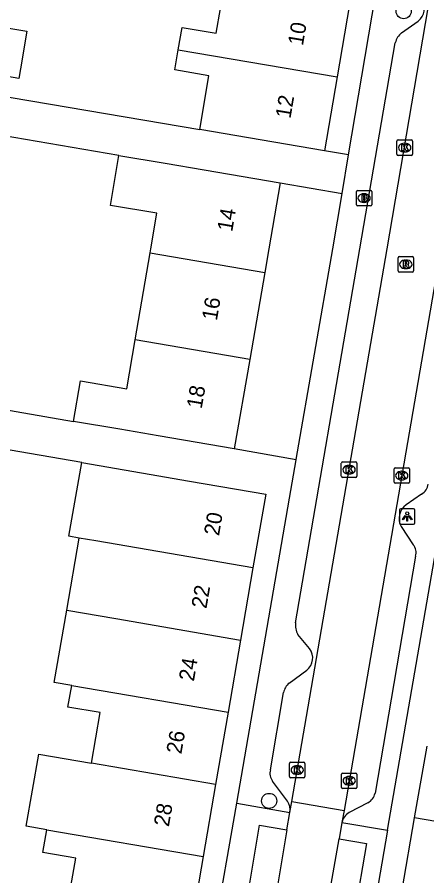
# Model space of a CAD drawing. Extents: x 159822 to 160765, y 380693 to 381634.
# Drawn here: x 160104.9 to 160131.4, y 380959.3 to 381015 of the extents above; entities that cross this region are included whole.
import ezdxf

# ---------------------------------------------------------------- set-up
doc = ezdxf.new("R2010")
doc.units = 0
for name, color, linetype in [('IMGEO_Boom', 7, 'Continuous'), ('IMGEO_Brandkraan', 7, 'Continuous'), ('IMGEO_Kolk', 7, 'Continuous'), ('IMGEO_Lichtpunt', 7, 'Continuous'), ('IMGEO_Pand', 7, 'Continuous'), ('IMGEO_Pand_nummerreeks', 7, 'Continuous'), ('IMGEO_Rijbaan_lokaal_open', 7, 'Continuous'), ('IMGEO_Rioolput', 7, 'Continuous'), ('IMGEO_Voetpad_open', 7, 'Continuous')]:
    doc.layers.add(name, color=color, linetype=linetype)

msp = doc.modelspace()

# ---------------------------------------------------------------- linework, layer by layer
at = {"layer": 'IMGEO_Boom'}
for centre in [(160129.945, 381015.406), (160121.229, 380964.193)]:
    msp.add_circle(centre, 0.489, dxfattribs=at)
at = {"layer": 'IMGEO_Brandkraan'}
for p, q in [((160126.879, 381002.859), (160126.879, 381003.711)), ((160126.954, 381003.785), (160127.806, 381003.785)), ((160127.367, 381003.565), (160127.392, 381003.565)), ((160127.88, 381003.711), (160127.88, 381002.859)), ((160127.39, 381003.005), (160127.365, 381003.005)), ((160127.806, 381002.785), (160126.954, 381002.785))]:
    msp.add_line(p, q, dxfattribs=at)
for points in [[(160126.879, 381002.859), (160126.879, 381003.711)], [(160126.954, 381003.785), (160127.806, 381003.785)], [(160127.88, 381003.711), (160127.88, 381002.859)], [(160127.227, 381003.485), (160127.227, 381003.085), (160127.44, 381003.085)], [(160127.458, 381003.485), (160127.227, 381003.485)], [(160127.406, 381003.404), (160127.352, 381003.404), (160127.352, 381003.328)], [(160127.352, 381003.328), (160127.405, 381003.328)], [(160127.414, 381003.252), (160127.352, 381003.252), (160127.352, 381003.171)], [(160127.352, 381003.171), (160127.414, 381003.171)], [(160127.806, 381002.785), (160126.954, 381002.785)]]:
    msp.add_lwpolyline(points, dxfattribs=at)
for centre, radius, start, end in [((160126.956, 381003.709), 0.0765, 91.552, 178.448), ((160126.956, 381003.709), 0.0765, 91.552, 178.448), ((160127.804, 381003.709), 0.0765, 1.552, 88.448), ((160127.804, 381003.709), 0.0765, 1.552, 88.448), ((160127.407, 381003.366), 0.0379, 267.8285, 90.9355), ((160127.415, 381003.211), 0.0404, 269.8759, 90.5077), ((160127.446, 381003.336), 0.251, 268.6676, 293.5347), ((160127.462, 381003.34), 0.145, 59.4692, 91.5367), ((160127.487, 381003.387), 0.0922, 285.5137, 58.1501), ((160127.492, 381003.195), 0.105, 301.3115, 78.989), ((160126.956, 381002.861), 0.0765, 181.552, 268.448), ((160126.956, 381002.861), 0.0765, 181.552, 268.448), ((160127.804, 381002.861), 0.0765, 271.552, 358.448), ((160127.804, 381002.861), 0.0765, 271.552, 358.448)]:
    msp.add_arc(centre, radius, start, end, dxfattribs=at)
for centre, major_axis, ratio, start_param, end_param in [((160127.366, 381003.285), (-0.387, 0.002), 0.722429, 4.712389, 7.853982), ((160127.391, 381003.285), (-0.39, 0.002), 0.717154, 1.570796, 4.712389)]:
    msp.add_ellipse(centre, major_axis=major_axis, ratio=ratio, start_param=start_param, end_param=end_param, dxfattribs=at)
at = {"layer": 'IMGEO_Kolk'}
for p, q in [((160129.51, 381006.134), (160129.51, 381006.986)), ((160129.585, 381007.06), (160130.437, 381007.06)), ((160130.511, 381006.986), (160130.511, 381006.134)), ((160129.998, 381006.84), (160130.023, 381006.84)), ((160130.437, 381006.06), (160129.585, 381006.06)), ((160130.021, 381006.28), (160129.996, 381006.28)), ((160125.907, 380985.249), (160125.907, 380986.101)), ((160125.982, 380986.175), (160126.834, 380986.175)), ((160126.395, 380985.955), (160126.42, 380985.955)), ((160126.908, 380986.101), (160126.908, 380985.249)), ((160129.321, 380984.867), (160129.321, 380985.719)), ((160129.396, 380985.793), (160130.248, 380985.793)), ((160130.322, 380985.719), (160130.322, 380984.867)), ((160126.834, 380985.175), (160125.982, 380985.175)), ((160126.418, 380985.395), (160126.393, 380985.395)), ((160129.809, 380985.573), (160129.834, 380985.573)), ((160130.248, 380984.793), (160129.396, 380984.793)), ((160129.832, 380985.013), (160129.807, 380985.013)), ((160122.547, 380965.769), (160122.547, 380966.621)), ((160122.622, 380966.695), (160123.474, 380966.695)), ((160123.035, 380966.475), (160123.06, 380966.475)), ((160123.548, 380966.621), (160123.548, 380965.769)), ((160123.474, 380965.695), (160122.622, 380965.695)), ((160123.058, 380965.915), (160123.033, 380965.915)), ((160125.916, 380965.07), (160125.916, 380965.922)), ((160125.991, 380965.996), (160126.843, 380965.996)), ((160126.404, 380965.776), (160126.429, 380965.776)), ((160126.917, 380965.922), (160126.917, 380965.07)), ((160126.427, 380965.216), (160126.402, 380965.216)), ((160126.843, 380964.996), (160125.991, 380964.996))]:
    msp.add_line(p, q, dxfattribs=at)
for points in [[(160129.51, 381006.134), (160129.51, 381006.986)], [(160129.585, 381007.06), (160130.437, 381007.06)], [(160130.511, 381006.986), (160130.511, 381006.134)], [(160129.831, 381006.76), (160129.954, 381006.76), (160129.954, 381006.609), (160130.084, 381006.76), (160130.248, 381006.76), (160130.102, 381006.609), (160130.255, 381006.36), (160130.103, 381006.36), (160130.018, 381006.524), (160129.954, 381006.457), (160129.954, 381006.36), (160129.831, 381006.36), (160129.831, 381006.76)], [(160130.437, 381006.06), (160129.585, 381006.06)], [(160125.907, 380985.249), (160125.907, 380986.101)], [(160125.982, 380986.175), (160126.834, 380986.175)], [(160126.228, 380985.875), (160126.351, 380985.875), (160126.351, 380985.724), (160126.481, 380985.875), (160126.645, 380985.875), (160126.499, 380985.724), (160126.652, 380985.475), (160126.5, 380985.475), (160126.415, 380985.639), (160126.351, 380985.572), (160126.351, 380985.475), (160126.228, 380985.475), (160126.228, 380985.875)], [(160126.908, 380986.101), (160126.908, 380985.249)], [(160129.321, 380984.867), (160129.321, 380985.719)], [(160129.396, 380985.793), (160130.248, 380985.793)], [(160130.322, 380985.719), (160130.322, 380984.867)], [(160126.834, 380985.175), (160125.982, 380985.175)], [(160129.642, 380985.493), (160129.765, 380985.493), (160129.765, 380985.342), (160129.895, 380985.493), (160130.059, 380985.493), (160129.913, 380985.342), (160130.066, 380985.093), (160129.914, 380985.093), (160129.829, 380985.257), (160129.765, 380985.19), (160129.765, 380985.093), (160129.642, 380985.093), (160129.642, 380985.493)], [(160130.248, 380984.793), (160129.396, 380984.793)], [(160122.547, 380965.769), (160122.547, 380966.621)], [(160122.622, 380966.695), (160123.474, 380966.695)], [(160122.868, 380966.395), (160122.991, 380966.395), (160122.991, 380966.244), (160123.121, 380966.395), (160123.285, 380966.395), (160123.139, 380966.244), (160123.292, 380965.995), (160123.14, 380965.995), (160123.055, 380966.159), (160122.991, 380966.092), (160122.991, 380965.995), (160122.868, 380965.995), (160122.868, 380966.395)], [(160123.548, 380966.621), (160123.548, 380965.769)], [(160123.474, 380965.695), (160122.622, 380965.695)], [(160125.916, 380965.07), (160125.916, 380965.922)], [(160125.991, 380965.996), (160126.843, 380965.996)], [(160126.237, 380965.696), (160126.36, 380965.696), (160126.36, 380965.545), (160126.49, 380965.696), (160126.654, 380965.696), (160126.508, 380965.545), (160126.661, 380965.296), (160126.509, 380965.296), (160126.424, 380965.46), (160126.36, 380965.393), (160126.36, 380965.296), (160126.237, 380965.296), (160126.237, 380965.696)], [(160126.917, 380965.922), (160126.917, 380965.07)], [(160126.843, 380964.996), (160125.991, 380964.996)]]:
    msp.add_lwpolyline(points, dxfattribs=at)
for centre, start, end in [((160129.587, 381006.984), 91.552, 178.448), ((160129.587, 381006.984), 91.552, 178.448), ((160130.435, 381006.984), 1.552, 88.448), ((160130.435, 381006.984), 1.552, 88.448), ((160129.587, 381006.136), 181.552, 268.448), ((160129.587, 381006.136), 181.552, 268.448), ((160130.435, 381006.136), 271.552, 358.448), ((160130.435, 381006.136), 271.552, 358.448), ((160125.984, 380986.099), 91.552, 178.448), ((160125.984, 380986.099), 91.552, 178.448), ((160126.832, 380986.099), 1.552, 88.448), ((160126.832, 380986.099), 1.552, 88.448), ((160129.398, 380985.717), 91.552, 178.448), ((160129.398, 380985.717), 91.552, 178.448), ((160130.246, 380985.717), 1.552, 88.448), ((160130.246, 380985.717), 1.552, 88.448), ((160125.984, 380985.251), 181.552, 268.448), ((160125.984, 380985.251), 181.552, 268.448), ((160126.832, 380985.251), 271.552, 358.448), ((160126.832, 380985.251), 271.552, 358.448), ((160129.398, 380984.869), 181.552, 268.448), ((160129.398, 380984.869), 181.552, 268.448), ((160130.246, 380984.869), 271.552, 358.448), ((160130.246, 380984.869), 271.552, 358.448), ((160122.624, 380966.619), 91.552, 178.448), ((160122.624, 380966.619), 91.552, 178.448), ((160123.472, 380966.619), 1.552, 88.448), ((160123.472, 380966.619), 1.552, 88.448), ((160122.624, 380965.771), 181.552, 268.448), ((160122.624, 380965.771), 181.552, 268.448), ((160123.472, 380965.771), 271.552, 358.448), ((160123.472, 380965.771), 271.552, 358.448), ((160125.993, 380965.92), 91.552, 178.448), ((160125.993, 380965.92), 91.552, 178.448), ((160126.841, 380965.92), 1.552, 88.448), ((160126.841, 380965.92), 1.552, 88.448), ((160125.993, 380965.072), 181.552, 268.448), ((160125.993, 380965.072), 181.552, 268.448), ((160126.841, 380965.072), 271.552, 358.448), ((160126.841, 380965.072), 271.552, 358.448)]:
    msp.add_arc(centre, 0.0765, start, end, dxfattribs=at)
for centre, major_axis, ratio, start_param, end_param in [((160129.997, 381006.56), (-0.387, 0.002), 0.722429, 4.712389, 7.853982), ((160130.022, 381006.56), (-0.39, 0.002), 0.717154, 1.570796, 4.712389), ((160126.394, 380985.675), (-0.387, 0.002), 0.722429, 4.712389, 7.853982), ((160126.419, 380985.675), (-0.39, 0.002), 0.717154, 1.570796, 4.712389), ((160129.808, 380985.293), (-0.387, 0.002), 0.722429, 4.712389, 7.853982), ((160129.833, 380985.293), (-0.39, 0.002), 0.717154, 1.570796, 4.712389), ((160123.034, 380966.195), (-0.387, 0.002), 0.722429, 4.712389, 7.853982), ((160123.059, 380966.195), (-0.39, 0.002), 0.717154, 1.570796, 4.712389), ((160126.403, 380965.496), (-0.387, 0.002), 0.722429, 4.712389, 7.853982), ((160126.428, 380965.496), (-0.39, 0.002), 0.717154, 1.570796, 4.712389)]:
    msp.add_ellipse(centre, major_axis=major_axis, ratio=ratio, start_param=start_param, end_param=end_param, dxfattribs=at)
at = {"layer": 'IMGEO_Lichtpunt'}
for p, q in [((160129.678, 380983.039), (160129.678, 380982.232)), ((160129.678, 380983.039), (160129.678, 380982.232)), ((160130.58, 380983.134), (160129.772, 380983.134)), ((160130.58, 380983.134), (160129.772, 380983.134)), ((160130.674, 380982.232), (160130.674, 380983.039)), ((160130.674, 380982.232), (160130.674, 380983.039)), ((160129.772, 380982.138), (160130.58, 380982.138)), ((160129.772, 380982.138), (160130.58, 380982.138))]:
    msp.add_line(p, q, dxfattribs=at)
for points in [[(160130.052, 380982.703), (160130.091, 380982.675), (160129.903, 380982.413), (160129.865, 380982.44), (160130.052, 380982.703)], [(160130.154, 380982.655), (160130.201, 380982.655), (160130.201, 380982.333), (160130.154, 380982.333), (160130.154, 380982.655)], [(160130.264, 380982.675), (160130.302, 380982.702), (160130.489, 380982.44), (160130.45, 380982.412), (160130.264, 380982.675)]]:
    msp.add_lwpolyline(points, dxfattribs=at)
msp.add_circle((160130.177, 380982.837), 0.0994, dxfattribs=at)
for centre, start, end in [((160129.772, 380983.039), 90, 180), ((160129.772, 380983.039), 90, 180), ((160130.58, 380983.039), 0, 90), ((160130.58, 380983.039), 0, 90), ((160129.772, 380982.232), 180, 270), ((160129.772, 380982.232), 180, 270), ((160130.58, 380982.232), 270, 0), ((160130.58, 380982.232), 270, 360)]:
    msp.add_arc(centre, 0.0946, start, end, dxfattribs=at)
at = {"layer": 'IMGEO_Pand'}
for points in [[(160115.347, 381012.91), (160115.593, 381014.354), (160117.806, 381013.976), (160118.359, 381017.215)], [(160126.434, 381015.835), (160125.634, 381011.153)], [(160103.071, 381014.534), (160105.535, 381014.112), (160105.118, 381011.678), (160105.01, 381011.047), (160102.548, 381011.47), (160102.821, 381013.068)], [(160116.737, 381007.729), (160117.334, 381011.222), (160115.123, 381011.6), (160115.347, 381012.91)], [(160115.347, 381012.91), (160125.634, 381011.153)], [(160125.634, 381011.153), (160124.813, 381006.349)], [(160124.813, 381006.349), (160119.885, 381007.191), (160116.737, 381007.729)], [(160113.513, 380999.74), (160113.557, 381000), (160113.95, 381002.304), (160110.944, 381002.818), (160111.498, 381006.056)], [(160111.498, 381006.056), (160114.502, 381005.543), (160117.017, 381005.113), (160121.945, 381004.271)], [(160121.945, 381004.271), (160121.209, 381000), (160120.944, 380998.46)], [(160112.551, 380994.1), (160113.513, 380999.74)], [(160113.513, 380999.74), (160120.944, 380998.46)], [(160120.944, 380998.46), (160119.973, 380992.822)], [(160108.566, 380988.808), (160109.018, 380991.434), (160112.008, 380990.919), (160112.551, 380994.1)], [(160119.973, 380992.822), (160112.551, 380994.1)], [(160119.973, 380992.822), (160118.973, 380987.015)], [(160118.973, 380987.015), (160114.046, 380987.864), (160111.56, 380988.292), (160108.566, 380988.808)], [(160108.925, 380981.239), (160108.262, 380981.353), (160109.089, 380986.143)], [(160109.089, 380986.143), (160112.968, 380985.475), (160116.082, 380984.939), (160121.009, 380984.09), (160120.184, 380979.3)], [(160108.119, 380976.558), (160108.925, 380981.239)], [(160120.184, 380979.3), (160109.994, 380981.055), (160108.925, 380981.239)], [(160120.184, 380979.3), (160119.378, 380974.619)], [(160108.44, 380971.682), (160107.313, 380971.876), (160108.119, 380976.558)], [(160108.119, 380976.558), (160111.294, 380976.011), (160119.378, 380974.619)], [(160119.378, 380974.619), (160118.572, 380969.938)], [(160109.713, 380966.643), (160110.277, 380969.921), (160108.198, 380970.279), (160108.44, 380971.682)], [(160108.44, 380971.682), (160118.572, 380969.938)], [(160118.572, 380969.938), (160117.766, 380965.256)], [(160130.656, 380963.083), (160131.459, 380967.745)], [(160106.829, 380962.32), (160105.5, 380962.549), (160106.307, 380967.23), (160109.713, 380966.643)], [(160117.766, 380965.256), (160109.713, 380966.643)], [(160117.766, 380965.256), (160116.96, 380960.575)], [(160129.853, 380958.422), (160130.656, 380963.083)], [(160138.691, 380961.7), (160130.656, 380963.083)], [(160108.129, 380957.163), (160108.701, 380960.485), (160106.576, 380960.851), (160106.829, 380962.32)], [(160106.829, 380962.32), (160116.96, 380960.575)], [(160116.96, 380960.575), (160116.135, 380955.784)]]:
    msp.add_lwpolyline(points, dxfattribs=at)
at = {"layer": 'IMGEO_Rijbaan_lokaal_open'}
for points in [[(160122.694, 380964.146), (160128.881, 381000), (160134.55, 381033.44)], [(160137.998, 381032.804), (160132.353, 381000), (160126.083, 380963.562)], [(160122.575, 380963.442), (160122.694, 380964.146)], [(160122.694, 380964.146), (160126.083, 380963.562)], [(160122.386, 380962.321), (160122.575, 380963.442)], [(160126.083, 380963.562), (160125.95, 380962.792)], [(160122.386, 380962.321), (160121.639, 380957.894)], [(160125.95, 380962.792), (160125.767, 380961.739)], [(160124.999, 380957.316), (160125.767, 380961.739)]]:
    msp.add_lwpolyline(points, dxfattribs=at)
at = {"layer": 'IMGEO_Rioolput'}
for p, q in [((160129.585, 380998.566), (160129.585, 380999.418)), ((160129.66, 380999.492), (160130.512, 380999.492)), ((160130.073, 380999.272), (160130.098, 380999.272)), ((160130.586, 380999.418), (160130.586, 380998.566)), ((160130.512, 380998.492), (160129.66, 380998.492)), ((160130.096, 380998.712), (160130.071, 380998.712))]:
    msp.add_line(p, q, dxfattribs=at)
for points in [[(160129.585, 380998.566), (160129.585, 380999.418)], [(160129.66, 380999.492), (160130.512, 380999.492)], [(160130.174, 380999.19), (160129.922, 380999.192), (160129.922, 380998.792)], [(160130.1, 380999.111), (160130.046, 380999.111), (160130.046, 380999.03)], [(160130.586, 380999.418), (160130.586, 380998.566)], [(160130.512, 380998.492), (160129.66, 380998.492)], [(160129.922, 380998.792), (160130.046, 380998.792), (160130.046, 380998.954), (160130.057, 380998.954)], [(160130.046, 380999.03), (160130.098, 380999.03)], [(160130.104, 380998.925), (160130.175, 380998.792), (160130.315, 380998.792), (160130.25, 380998.918)]]:
    msp.add_lwpolyline(points, dxfattribs=at)
for centre, radius, start, end in [((160129.662, 380999.416), 0.0765, 91.552, 178.448), ((160129.662, 380999.416), 0.0765, 91.552, 178.448), ((160130.106, 380999.015), 0.0964, 77.0061, 93.1865), ((160130.12, 380999.072), 0.0378, 276.6634, 79.6772), ((160130.173, 380999.08), 0.109, 350.3612, 89.416), ((160130.171, 380999.08), 0.112, 277.5842, 350.9817), ((160130.51, 380999.416), 0.0765, 1.552, 88.448), ((160130.51, 380999.416), 0.0765, 1.552, 88.448), ((160129.662, 380998.568), 0.0765, 181.552, 268.448), ((160129.662, 380998.568), 0.0765, 181.552, 268.448), ((160130.056, 380998.901), 0.0533, 26.0293, 88.6989), ((160130.082, 380999.219), 0.19, 274.7715, 282.9687), ((160130.155, 380998.865), 0.108, 29.5134, 73.7905), ((160130.51, 380998.568), 0.0765, 271.552, 358.448), ((160130.51, 380998.568), 0.0765, 271.552, 358.448)]:
    msp.add_arc(centre, radius, start, end, dxfattribs=at)
for centre, major_axis, ratio, start_param, end_param in [((160130.072, 380998.992), (-0.387, 0.002), 0.722429, 4.712389, 7.853982), ((160130.097, 380998.992), (-0.39, 0.002), 0.717154, 1.570796, 4.712389)]:
    msp.add_ellipse(centre, major_axis=major_axis, ratio=ratio, start_param=start_param, end_param=end_param, dxfattribs=at)
at = {"layer": 'IMGEO_Voetpad_open'}
for points in [[(160126.379, 381006.084), (160131.175, 381034.429)], [(160129.809, 381014.001), (160130.891, 381014.769)], [(160102.582, 381013.11), (160102.088, 381010.233), (160116.737, 381007.729)], [(160122.948, 380975.751), (160127.111, 381000), (160129.403, 381013.355)], [(160111.498, 381006.056), (160101.651, 381007.738), (160101.342, 381005.857), (160100.698, 381001.943), (160100.177, 380998.779), (160099.688, 380996.187), (160099.421, 380994.563), (160099.153, 380992.939), (160098.75, 380990.5), (160108.566, 380988.808)], [(160126.379, 381006.084), (160124.813, 381006.349)], [(160125.958, 381003.592), (160126.379, 381006.084)], [(160121.945, 381004.271), (160125.958, 381003.592)], [(160122.983, 380986.32), (160122.984, 380986.324), (160125.35, 381000), (160125.958, 381003.592)], [(160109.089, 380986.143), (160098.284, 380988.003), (160098.209, 380987.544), (160097.503, 380983.206), (160097.248, 380981.638), (160096.992, 380980.069), (160096.607, 380978.179), (160095.901, 380973.842)], [(160122.983, 380986.32), (160118.973, 380987.015)], [(160119.128, 380964.039), (160122.551, 380983.824), (160122.983, 380986.32)], [(160131.107, 380984.085), (160130.108, 380983.389)], [(160128.898, 380962.283), (160132.329, 380982.168)], [(160129.792, 380981.979), (160130.554, 380980.808)], [(160130.718, 380980.059), (160128.088, 380964.69)], [(160123.854, 380974.072), (160123.094, 380974.978)], [(160122.531, 380971.838), (160123.662, 380972.67)], [(160121.316, 380966.216), (160122.166, 380971.213)], [(160122.427, 380964.172), (160121.452, 380965.464)], [(160117.654, 380955.521), (160119.128, 380964.039)], [(160119.128, 380964.039), (160122.575, 380963.442)], [(160127.628, 380964.069), (160126.408, 380963.436)], [(160121.639, 380957.894), (160119.865, 380958.199), (160120.614, 380962.627), (160122.386, 380962.321)], [(160125.95, 380962.792), (160128.898, 380962.283)], [(160125.767, 380961.739), (160127.537, 380961.434), (160126.775, 380957.01), (160124.999, 380957.316)], [(160128.898, 380962.283), (160127.445, 380953.861)]]:
    msp.add_lwpolyline(points, dxfattribs=at)
for centre, radius, start, end in [((160130.241, 381015.588), 1.046, 308.452, 33.1715), ((160130.48, 381013.129), 1.1, 127.5615, 168.1412), ((160130.674, 380984.829), 0.861, 300.2167, 354.0745), ((160130.697, 380982.517), 1.053, 124.0382, 210.6977), ((160129.929, 380980.279), 0.819, 344.4498, 40.2512), ((160124.256, 380975.598), 1.317, 173.3182, 208.0732), ((160123.056, 380973.467), 1.001, 307.2474, 37.1566), ((160123.232, 380971.009), 1.086, 130.2456, 169.1845), ((160122.153, 380965.979), 0.869, 164.1817, 216.3207), ((160127.214, 380964.856), 0.89, 297.7267, 349.2156), ((160121.459, 380963.596), 1.126, 352.1544, 30.7672), ((160126.883, 380962.613), 0.95, 120.0159, 169.1448)]:
    msp.add_arc(centre, radius, start, end, dxfattribs=at)

# ---------------------------------------------------------------- texts
at = {"layer": 'IMGEO_Pand_nummerreeks'}
for s, rotation, p in [('10', 80.3034, (160123.417, 381013.137)), ('12', 80.3034, (160122.609, 381008.408)), ('14', 80.2278, (160118.837, 381001.069)), ('16', 80.2278, (160117.843, 380995.302)), ('18', 80.2278, (160116.858, 380989.582)), ('20', 80.2313, (160117.98, 380981.348)), ('22', 80.2313, (160117.167, 380976.625)), ('24', 80.2301, (160116.354, 380971.91)), ('26', 80.2301, (160115.542, 380967.192)), ('28', 80.2313, (160114.731, 380962.478))]:
    msp.add_text(s, height=1, rotation=rotation, dxfattribs=at).set_placement(p)

doc.saveas('drawing.dxf')
